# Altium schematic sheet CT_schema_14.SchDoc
size 389 x 385 mm
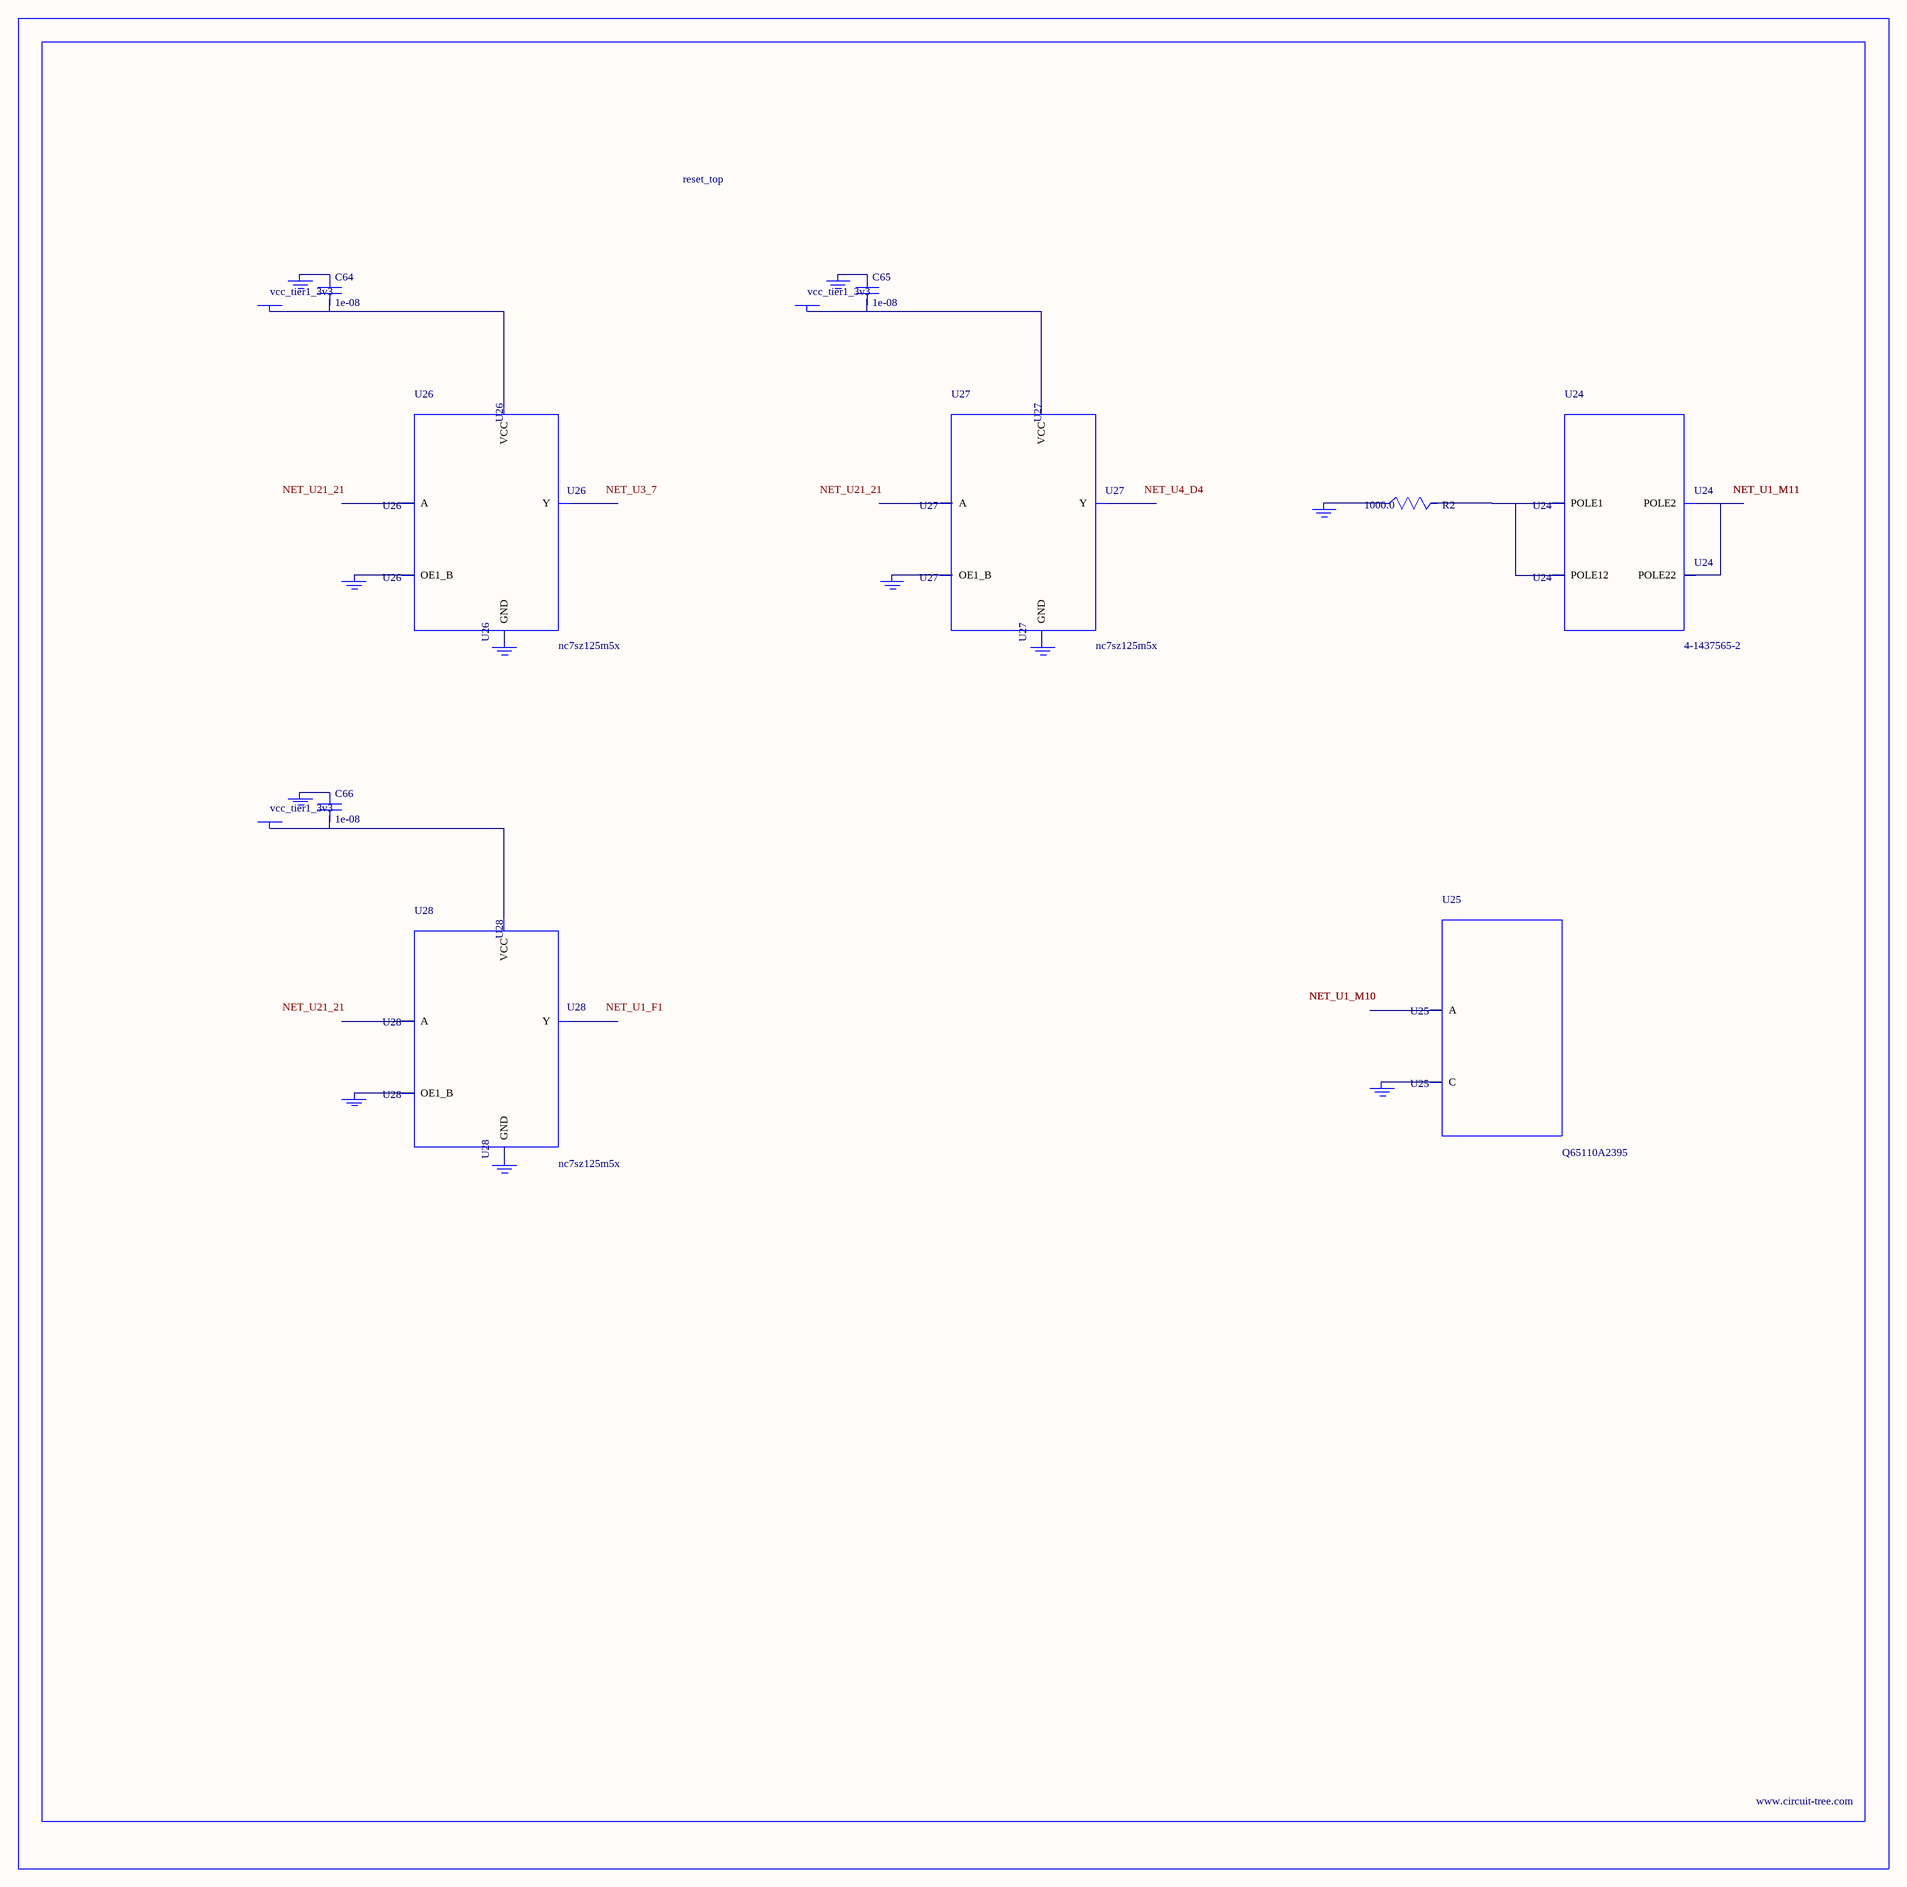
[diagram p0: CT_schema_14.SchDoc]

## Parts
BORDER13  (no value)
C64  1e-08  [C0402]
C65  1e-08  [C0402]
C66  1e-08  [C0402]
GND_INSTANCE_13_0  (no value)
GND_INSTANCE_13_1  (no value)
GND_INSTANCE_13_2  (no value)
GND_INSTANCE_13_3  (no value)
GND_INSTANCE_13_4  (no value)
GND_INSTANCE_13_5  (no value)
GND_INSTANCE_13_6  (no value)
GND_INSTANCE_13_7  (no value)
GND_INSTANCE_13_8  (no value)
GND_INSTANCE_13_9  (no value)
GND_INSTANCE_13_10  (no value)
POWER_INSTANCE_13_0  vcc_tier1_3v3
POWER_INSTANCE_13_1  vcc_tier1_3v3
POWER_INSTANCE_13_2  vcc_tier1_3v3
R2  1000.0  [R0603]
U24  4-1437565-2  [SW_4-1437565-2]
U25  Q65110A2395  [LGM67K-G1J2-24-Z]
U26  nc7sz125m5x  [NC7SZ125M5X]
U27  nc7sz125m5x  [NC7SZ125M5X]
U28  nc7sz125m5x  [NC7SZ125M5X]

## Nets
NetC64_1: C64.1 GND_INSTANCE_13_2.0(GND)
NetC64_2: C64.2 POWER_INSTANCE_13_0.0(PWR) U26.5(VCC)
NetC65_1: C65.1 GND_INSTANCE_13_5.0(GND)
NetC65_2: C65.2 POWER_INSTANCE_13_1.0(PWR) U27.5(VCC)
NetC66_1: C66.1 GND_INSTANCE_13_8.0(GND)
NetC66_2: C66.2 POWER_INSTANCE_13_2.0(PWR) U28.5(VCC)
NetGND_INSTANCE_13_0_0: GND_INSTANCE_13_0.0(GND) R2.1
NetGND_INSTANCE_13_1_0: GND_INSTANCE_13_1.0(GND) U25.C
NetGND_INSTANCE_13_3_0: GND_INSTANCE_13_3.0(GND) U26.1(OE1_B)
NetGND_INSTANCE_13_4_0: GND_INSTANCE_13_4.0(GND) U26.3(GND)
NetGND_INSTANCE_13_6_0: GND_INSTANCE_13_6.0(GND) U27.1(OE1_B)
NetGND_INSTANCE_13_7_0: GND_INSTANCE_13_7.0(GND) U27.3(GND)
NetGND_INSTANCE_13_9_0: GND_INSTANCE_13_9.0(GND) U28.1(OE1_B)
NetGND_INSTANCE_13_10_0: GND_INSTANCE_13_10.0(GND) U28.3(GND)
NetR2_2: R2.2 U24.1(POLE1) U24.2(POLE12)
NetU24_3: U24.3(POLE2) U24.4(POLE22)

Not connected (* = marked no-connect by the designer): U25 A; U26 2(A) 4(Y); U27 2(A) 4(Y); U28 2(A) 4(Y)

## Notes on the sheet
- Labels drawn without touching a wire or pin: NET_U1_F1, NET_U3_7, NET_U4_D4, NET_U21_21

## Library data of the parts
BORDER13 = BORDER_PAGE13
C64-C66 = C0402C103K3RAC
GND_INSTANCE_13_0-GND_INSTANCE_13_10 = GND
POWER_INSTANCE_13_0-POWER_INSTANCE_13_2 = PWR
R2 = RC0603JR-071KL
